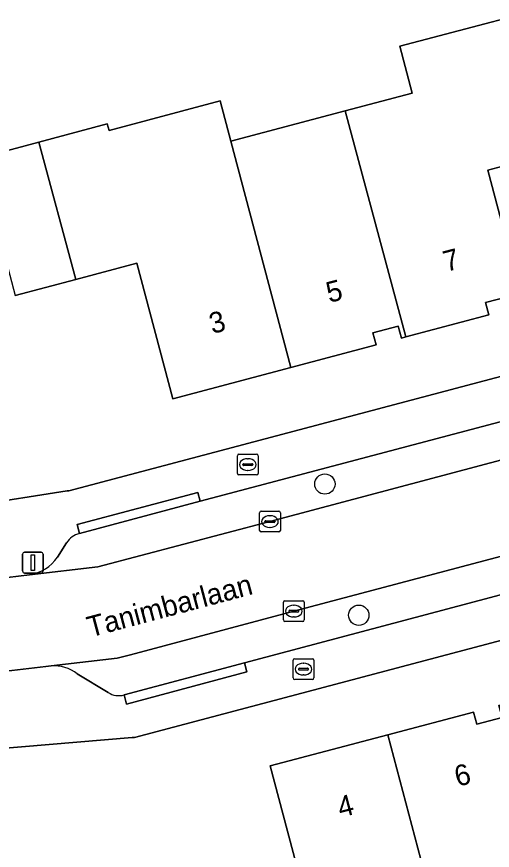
# Model space of a CAD drawing. Extents: x 162879 to 165540, y 384011 to 385181.
# Drawn here: x 163822.64 to 163845.56, y 384364.78 to 384404.9 of the extents above; entities that cross this region are included whole.
import ezdxf

# ---------------------------------------------------------------- set-up
doc = ezdxf.new("R2010")
doc.units = 0
for name, color, linetype in [('IMGEO_Boom', 7, 'Continuous'), ('IMGEO_Brandkraan', 7, 'Continuous'), ('IMGEO_Erf', 7, 'Continuous'), ('IMGEO_Kolk', 7, 'Continuous'), ('IMGEO_Lichtmast', 7, 'Continuous'), ('IMGEO_Muur', 7, 'Continuous'), ('IMGEO_Openbare_ruimte_label', 7, 'Continuous'), ('IMGEO_Pand', 7, 'Continuous'), ('IMGEO_Pand_nummerreeks', 7, 'Continuous'), ('IMGEO_Parkeervlak_open', 7, 'Continuous'), ('IMGEO_Rijbaan_lokaal_open', 7, 'Continuous'), ('IMGEO_Voetpad_open', 7, 'Continuous')]:
    doc.layers.add(name, color=color, linetype=linetype)

msp = doc.modelspace()

# ---------------------------------------------------------------- linework, layer by layer
at = {"layer": 'IMGEO_Boom'}
for centre in [(163837.49, 384382.411), (163839.124, 384376.096)]:
    msp.add_circle(centre, 0.489, dxfattribs=at)
at = {"layer": 'IMGEO_Brandkraan'}
for p, q in [((163833.274, 384382.922), (163833.274, 384383.774)), ((163833.349, 384383.848), (163834.201, 384383.848)), ((163833.762, 384383.628), (163833.787, 384383.628)), ((163834.275, 384383.774), (163834.275, 384382.922)), ((163833.533, 384383.342), (163833.533, 384383.354)), ((163833.971, 384383.305), (163833.573, 384383.305)), ((163833.576, 384383.391), (163833.974, 384383.391)), ((163834.017, 384383.354), (163834.017, 384383.342)), ((163834.201, 384382.848), (163833.349, 384382.848)), ((163833.785, 384383.068), (163833.76, 384383.068)), ((163836.035, 384374.004), (163836.887, 384374.004)), ((163835.96, 384373.078), (163835.96, 384373.93)), ((163836.448, 384373.784), (163836.473, 384373.784)), ((163836.961, 384373.93), (163836.961, 384373.078)), ((163836.219, 384373.498), (163836.219, 384373.51)), ((163836.657, 384373.461), (163836.259, 384373.461)), ((163836.262, 384373.547), (163836.66, 384373.547)), ((163836.471, 384373.224), (163836.446, 384373.224)), ((163836.703, 384373.51), (163836.703, 384373.498)), ((163836.887, 384373.004), (163836.035, 384373.004))]:
    msp.add_line(p, q, dxfattribs=at)
for points in [[(163833.274, 384382.922), (163833.274, 384383.774)], [(163833.349, 384383.848), (163834.201, 384383.848)], [(163834.275, 384383.774), (163834.275, 384382.922)], [(163834.201, 384382.848), (163833.349, 384382.848)], [(163836.035, 384374.004), (163836.887, 384374.004)], [(163835.96, 384373.078), (163835.96, 384373.93)], [(163836.961, 384373.93), (163836.961, 384373.078)], [(163836.887, 384373.004), (163836.035, 384373.004)]]:
    msp.add_lwpolyline(points, dxfattribs=at)
for centre, radius, start, end in [((163833.351, 384383.772), 0.0765, 91.552, 178.448), ((163833.351, 384383.772), 0.0765, 91.552, 178.448), ((163834.199, 384383.772), 0.0765, 1.552, 88.448), ((163834.199, 384383.772), 0.0765, 1.552, 88.448), ((163833.573, 384383.351), 0.0403, 85.8775, 175.7526), ((163833.57, 384383.341), 0.0366, 178.938, 274.7102), ((163833.974, 384383.348), 0.043, 264.8664, 352.4533), ((163833.978, 384383.353), 0.0386, 1.7309, 96.639), ((163833.351, 384382.924), 0.0765, 181.552, 268.448), ((163833.351, 384382.924), 0.0765, 181.552, 268.448), ((163834.199, 384382.924), 0.0765, 271.552, 358.448), ((163834.199, 384382.924), 0.0765, 271.552, 358.448), ((163836.037, 384373.928), 0.0765, 91.552, 178.448), ((163836.037, 384373.928), 0.0765, 91.552, 178.448), ((163836.885, 384373.928), 0.0765, 1.552, 88.448), ((163836.885, 384373.928), 0.0765, 1.552, 88.448), ((163836.259, 384373.507), 0.0403, 85.8775, 175.7526), ((163836.256, 384373.497), 0.0366, 178.938, 274.7102), ((163836.66, 384373.504), 0.043, 264.8664, 352.4533), ((163836.664, 384373.509), 0.0386, 1.7309, 96.639), ((163836.037, 384373.08), 0.0765, 181.552, 268.448), ((163836.037, 384373.08), 0.0765, 181.552, 268.448), ((163836.885, 384373.08), 0.0765, 271.552, 358.448), ((163836.885, 384373.08), 0.0765, 271.552, 358.448)]:
    msp.add_arc(centre, radius, start, end, dxfattribs=at)
for centre, major_axis, ratio, start_param, end_param in [((163833.761, 384383.348), (-0.387, 0.002), 0.722429, 4.712389, 7.853982), ((163833.786, 384383.348), (-0.39, 0.002), 0.717154, 1.570796, 4.712389), ((163836.447, 384373.504), (-0.387, 0.002), 0.722429, 4.712389, 7.853982), ((163836.472, 384373.504), (-0.39, 0.002), 0.717154, 1.570796, 4.712389)]:
    msp.add_ellipse(centre, major_axis=major_axis, ratio=ratio, start_param=start_param, end_param=end_param, dxfattribs=at)
at = {"layer": 'IMGEO_Erf'}
for points in [[(163820.82, 384398.098), (163823.706, 384398.863), (163827.007, 384399.738), (163827.089, 384399.429), (163832.445, 384400.849), (163832.96, 384398.908), (163838.461, 384400.366), (163841.699, 384401.225), (163841.103, 384403.478), (163844.892, 384404.481), (163846.484, 384404.902)], [(163848.238, 384398.285), (163845.347, 384397.519), (163846.918, 384391.573), (163845.236, 384391.141), (163845.392, 384390.551), (163841.393, 384389.491), (163841.178, 384389.434), (163841.025, 384390.014), (163839.807, 384389.692), (163839.96, 384389.111), (163835.849, 384388.021), (163830.158, 384386.513), (163828.429, 384393.038), (163825.485, 384392.258), (163822.572, 384391.486)], [(163802.92, 384378.611), (163816.096, 384380.674), (163825.065, 384382.078), (163825.148, 384382.091), (163865.727, 384392.809)], [(163871.845, 384381.733), (163828.311, 384370.22), (163828.207, 384370.211), (163817.519, 384369.317), (163804.137, 384368.197)], [(163836.581, 384362.317), (163834.857, 384368.843), (163840.521, 384370.34), (163844.652, 384371.431), (163844.806, 384370.851), (163846.024, 384371.173), (163845.87, 384371.752), (163846.054, 384371.801), (163850.085, 384372.866), (163850.239, 384372.286), (163851.923, 384372.725), (163853.501, 384366.787), (163856.396, 384367.552), (163859.302, 384368.319), (163857.713, 384374.261), (163859.394, 384374.711), (163859.239, 384375.291), (163863.228, 384376.343), (163863.455, 384376.403), (163863.608, 384375.823), (163864.827, 384376.144), (163864.674, 384376.725), (163868.771, 384377.805), (163874.486, 384379.311)]]:
    msp.add_lwpolyline(points, dxfattribs=at)
at = {"layer": 'IMGEO_Kolk'}
for p, q in [((163834.343, 384380.178), (163834.343, 384381.03)), ((163834.418, 384381.104), (163835.27, 384381.104)), ((163834.831, 384380.884), (163834.856, 384380.884)), ((163835.344, 384381.03), (163835.344, 384380.178)), ((163834.602, 384380.598), (163834.602, 384380.61)), ((163835.04, 384380.561), (163834.642, 384380.561)), ((163834.645, 384380.647), (163835.043, 384380.647)), ((163835.086, 384380.61), (163835.086, 384380.598)), ((163835.27, 384380.104), (163834.418, 384380.104)), ((163834.854, 384380.324), (163834.829, 384380.324)), ((163835.567, 384376.795), (163836.419, 384376.795)), ((163835.492, 384375.869), (163835.492, 384376.721)), ((163835.98, 384376.575), (163836.005, 384376.575)), ((163836.493, 384376.721), (163836.493, 384375.869)), ((163835.751, 384376.289), (163835.751, 384376.301)), ((163836.189, 384376.252), (163835.791, 384376.252)), ((163835.794, 384376.338), (163836.192, 384376.338)), ((163836.003, 384376.015), (163835.978, 384376.015)), ((163836.235, 384376.301), (163836.235, 384376.289)), ((163836.419, 384375.795), (163835.567, 384375.795))]:
    msp.add_line(p, q, dxfattribs=at)
for points in [[(163834.343, 384380.178), (163834.343, 384381.03)], [(163834.418, 384381.104), (163835.27, 384381.104)], [(163835.344, 384381.03), (163835.344, 384380.178)], [(163835.27, 384380.104), (163834.418, 384380.104)], [(163835.567, 384376.795), (163836.419, 384376.795)], [(163835.492, 384375.869), (163835.492, 384376.721)], [(163836.493, 384376.721), (163836.493, 384375.869)], [(163836.419, 384375.795), (163835.567, 384375.795)]]:
    msp.add_lwpolyline(points, dxfattribs=at)
for centre, radius, start, end in [((163834.42, 384381.028), 0.0765, 91.552, 178.448), ((163834.42, 384381.028), 0.0765, 91.552, 178.448), ((163835.268, 384381.028), 0.0765, 1.552, 88.448), ((163835.268, 384381.028), 0.0765, 1.552, 88.448), ((163834.642, 384380.607), 0.0403, 85.8775, 175.7526), ((163834.639, 384380.597), 0.0366, 178.938, 274.7102), ((163835.043, 384380.604), 0.043, 264.8664, 352.4533), ((163835.047, 384380.609), 0.0386, 1.7309, 96.639), ((163834.42, 384380.18), 0.0765, 181.552, 268.448), ((163834.42, 384380.18), 0.0765, 181.552, 268.448), ((163835.268, 384380.18), 0.0765, 271.552, 358.448), ((163835.268, 384380.18), 0.0765, 271.552, 358.448), ((163835.569, 384376.719), 0.0765, 91.552, 178.448), ((163835.569, 384376.719), 0.0765, 91.552, 178.448), ((163836.417, 384376.719), 0.0765, 1.552, 88.448), ((163836.417, 384376.719), 0.0765, 1.552, 88.448), ((163835.791, 384376.298), 0.0403, 85.8775, 175.7526), ((163835.788, 384376.288), 0.0366, 178.938, 274.7102), ((163836.192, 384376.295), 0.043, 264.8664, 352.4533), ((163836.196, 384376.3), 0.0386, 1.7309, 96.639), ((163835.569, 384375.871), 0.0765, 181.552, 268.448), ((163835.569, 384375.871), 0.0765, 181.552, 268.448), ((163836.417, 384375.871), 0.0765, 271.552, 358.448), ((163836.417, 384375.871), 0.0765, 271.552, 358.448)]:
    msp.add_arc(centre, radius, start, end, dxfattribs=at)
for centre, major_axis, ratio, start_param, end_param in [((163834.83, 384380.604), (-0.387, 0.002), 0.722429, 4.712389, 7.853982), ((163834.855, 384380.604), (-0.39, 0.002), 0.717154, 1.570796, 4.712389), ((163835.979, 384376.295), (-0.387, 0.002), 0.722429, 4.712389, 7.853982), ((163836.004, 384376.295), (-0.39, 0.002), 0.717154, 1.570796, 4.712389)]:
    msp.add_ellipse(centre, major_axis=major_axis, ratio=ratio, start_param=start_param, end_param=end_param, dxfattribs=at)
at = {"layer": 'IMGEO_Lichtmast'}
for p, q in [((163822.923, 384378.23), (163822.923, 384379.03)), ((163822.923, 384379.03), (163822.923, 384378.23)), ((163823.023, 384379.13), (163823.813, 384379.13)), ((163823.813, 384379.13), (163823.023, 384379.13)), ((163823.913, 384379.03), (163823.913, 384378.23)), ((163823.913, 384378.23), (163823.913, 384379.03)), ((163823.813, 384378.13), (163823.023, 384378.13)), ((163823.023, 384378.13), (163823.813, 384378.13))]:
    msp.add_line(p, q, dxfattribs=at)
msp.add_lwpolyline([(163823.343, 384379.005), (163823.493, 384379.005), (163823.493, 384378.255), (163823.343, 384378.255), (163823.343, 384379.005)], dxfattribs=at)
for centre, start, end in [((163823.023, 384379.03), 90, 180), ((163823.023, 384379.03), 90, 180), ((163823.813, 384379.03), 0, 90), ((163823.813, 384379.03), 360, 90), ((163823.023, 384378.23), 180, 270), ((163823.023, 384378.23), 180, 270), ((163823.813, 384378.23), 270, 0), ((163823.813, 384378.23), 270, 0)]:
    msp.add_arc(centre, 0.1, start, end, dxfattribs=at)
at = {"layer": 'IMGEO_Muur'}
for points in [[(163816.096, 384380.674), (163825.065, 384382.078)], [(163817.519, 384369.317), (163828.207, 384370.211)]]:
    msp.add_lwpolyline(points, dxfattribs=at)
at = {"layer": 'IMGEO_Pand'}
for points in [[(163841.393, 384389.491), (163845.392, 384390.551), (163845.236, 384391.141), (163846.918, 384391.573), (163845.347, 384397.519), (163848.238, 384398.285), (163846.484, 384404.902), (163844.892, 384404.481), (163841.103, 384403.478), (163841.699, 384401.225), (163838.461, 384400.366)], [(163832.96, 384398.908), (163832.445, 384400.849), (163827.089, 384399.429), (163827.007, 384399.738), (163823.706, 384398.863), (163825.485, 384392.258), (163828.429, 384393.038), (163830.158, 384386.513), (163835.849, 384388.021)], [(163832.96, 384398.908), (163835.849, 384388.021), (163839.96, 384389.111), (163839.807, 384389.692), (163841.025, 384390.014), (163841.178, 384389.434), (163841.393, 384389.491), (163838.461, 384400.366)], [(163823.706, 384398.863), (163820.82, 384398.098), (163822.572, 384391.486), (163825.485, 384392.258)], [(163846.054, 384371.801), (163845.87, 384371.752), (163846.024, 384371.173), (163844.806, 384370.851), (163844.652, 384371.431), (163840.521, 384370.34), (163843.411, 384359.436), (163848.944, 384360.897)], [(163835.374, 384354.903), (163838.643, 384355.767), (163838.048, 384358.02), (163843.411, 384359.436), (163840.521, 384370.34), (163834.857, 384368.843), (163836.581, 384362.317), (163833.617, 384361.534)]]:
    msp.add_lwpolyline(points, close=True, dxfattribs=at)
at = {"layer": 'IMGEO_Parkeervlak_open'}
for points in [[(163864.892, 384390.413), (163854.243, 384387.611), (163848.431, 384386.065), (163831.487, 384381.581), (163825.666, 384380.027)], [(163823.263, 384378.046), (163826.557, 384378.434), (163834.844, 384380.604), (163865.713, 384388.799)], [(163869.972, 384385.282), (163867.877, 384384.716), (163851.935, 384380.508), (163835.992, 384376.295), (163828.118, 384374.191), (163827.488, 384374.039), (163824.303, 384373.665)], [(163827.817, 384372.265), (163833.614, 384373.811), (163850.07, 384378.169), (163855.892, 384379.711), (163867.495, 384382.781)], [(163825.046, 384379.585), (163824.603, 384378.892)], [(163825.561, 384373.28), (163827.049, 384372.38)]]:
    msp.add_lwpolyline(points, dxfattribs=at)
for centre, radius, start, end in [((163825.904, 384379.037), 1.019, 103.539, 147.4314), ((163822.981, 384379.977), 1.951, 278.3078, 326.2242), ((163824.401, 384371.738), 1.929, 53.0471, 92.9204), ((163827.559, 384373.163), 0.934, 236.9273, 286.0403)]:
    msp.add_arc(centre, radius, start, end, dxfattribs=at)
at = {"layer": 'IMGEO_Rijbaan_lokaal_open'}
for points in [[(163868.168, 384389.455), (163865.713, 384388.799), (163834.844, 384380.604), (163826.557, 384378.434), (163823.263, 384378.046), (163821.656, 384377.851), (163803.948, 384375.773), (163802.736, 384375.641)], [(163835.992, 384376.295), (163851.935, 384380.508), (163867.877, 384384.716), (163869.972, 384385.282), (163870.228, 384385.351), (163871.192, 384385.606)], [(163803.596, 384371.169), (163804.511, 384371.285), (163821.852, 384373.367), (163824.051, 384373.635), (163824.303, 384373.665), (163827.488, 384374.039), (163828.118, 384374.191), (163835.992, 384376.295)]]:
    msp.add_lwpolyline(points, dxfattribs=at)
at = {"layer": 'IMGEO_Voetpad_open'}
for points in [[(163865.727, 384392.809), (163825.148, 384382.091), (163825.065, 384382.078), (163816.096, 384380.674), (163802.92, 384378.611)], [(163825.666, 384380.027), (163825.558, 384380.472), (163831.374, 384382.003), (163831.487, 384381.581), (163848.431, 384386.065), (163848.312, 384386.508), (163854.132, 384388.038), (163854.243, 384387.611), (163864.892, 384390.413)], [(163867.495, 384382.781), (163855.892, 384379.711), (163855.992, 384379.282), (163850.195, 384377.738), (163850.07, 384378.169), (163833.614, 384373.811), (163833.732, 384373.38), (163827.925, 384371.825), (163827.817, 384372.265)], [(163804.137, 384368.197), (163817.519, 384369.317), (163828.207, 384370.211), (163828.311, 384370.22), (163871.845, 384381.733)], [(163824.603, 384378.892), (163825.046, 384379.585)], [(163802.736, 384375.641), (163803.948, 384375.773), (163821.656, 384377.851), (163823.263, 384378.046)], [(163824.303, 384373.665), (163824.051, 384373.635), (163821.852, 384373.367), (163804.511, 384371.285), (163803.596, 384371.169)], [(163827.049, 384372.38), (163825.561, 384373.28)]]:
    msp.add_lwpolyline(points, dxfattribs=at)
for points in [[(163825.666, 384380.027), (163831.487, 384381.581), (163831.374, 384382.003), (163825.558, 384380.472)], [(163827.817, 384372.265), (163827.925, 384371.825), (163833.732, 384373.38), (163833.614, 384373.811)]]:
    msp.add_lwpolyline(points, close=True, dxfattribs=at)
for centre, radius, start, end in [((163825.904, 384379.037), 1.019, 103.539, 147.4314), ((163822.981, 384379.977), 1.951, 278.3078, 326.2242), ((163824.401, 384371.738), 1.929, 53.0471, 92.9204), ((163827.559, 384373.163), 0.934, 236.9273, 286.0403)]:
    msp.add_arc(centre, radius, start, end, dxfattribs=at)

# ---------------------------------------------------------------- texts
at = {"layer": 'IMGEO_Openbare_ruimte_label'}
msp.add_text('Tanimbarlaan', height=1, rotation=14.8982, dxfattribs=at).set_placement((163826.182, 384375.026))
at = {"layer": 'IMGEO_Pand_nummerreeks'}
for s, rotation, p in [('7', 14.8457, (163843.34, 384392.615)), ('5', 14.8457, (163837.702, 384391.121)), ('3', 14.8457, (163832.065, 384389.626)), ('6', 14.7991, (163843.884, 384367.836)), ('4', 14.7991, (163838.247, 384366.347))]:
    msp.add_text(s, height=1, rotation=rotation, dxfattribs=at).set_placement(p)

doc.saveas('drawing.dxf')
